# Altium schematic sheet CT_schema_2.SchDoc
size 362 x 192 mm
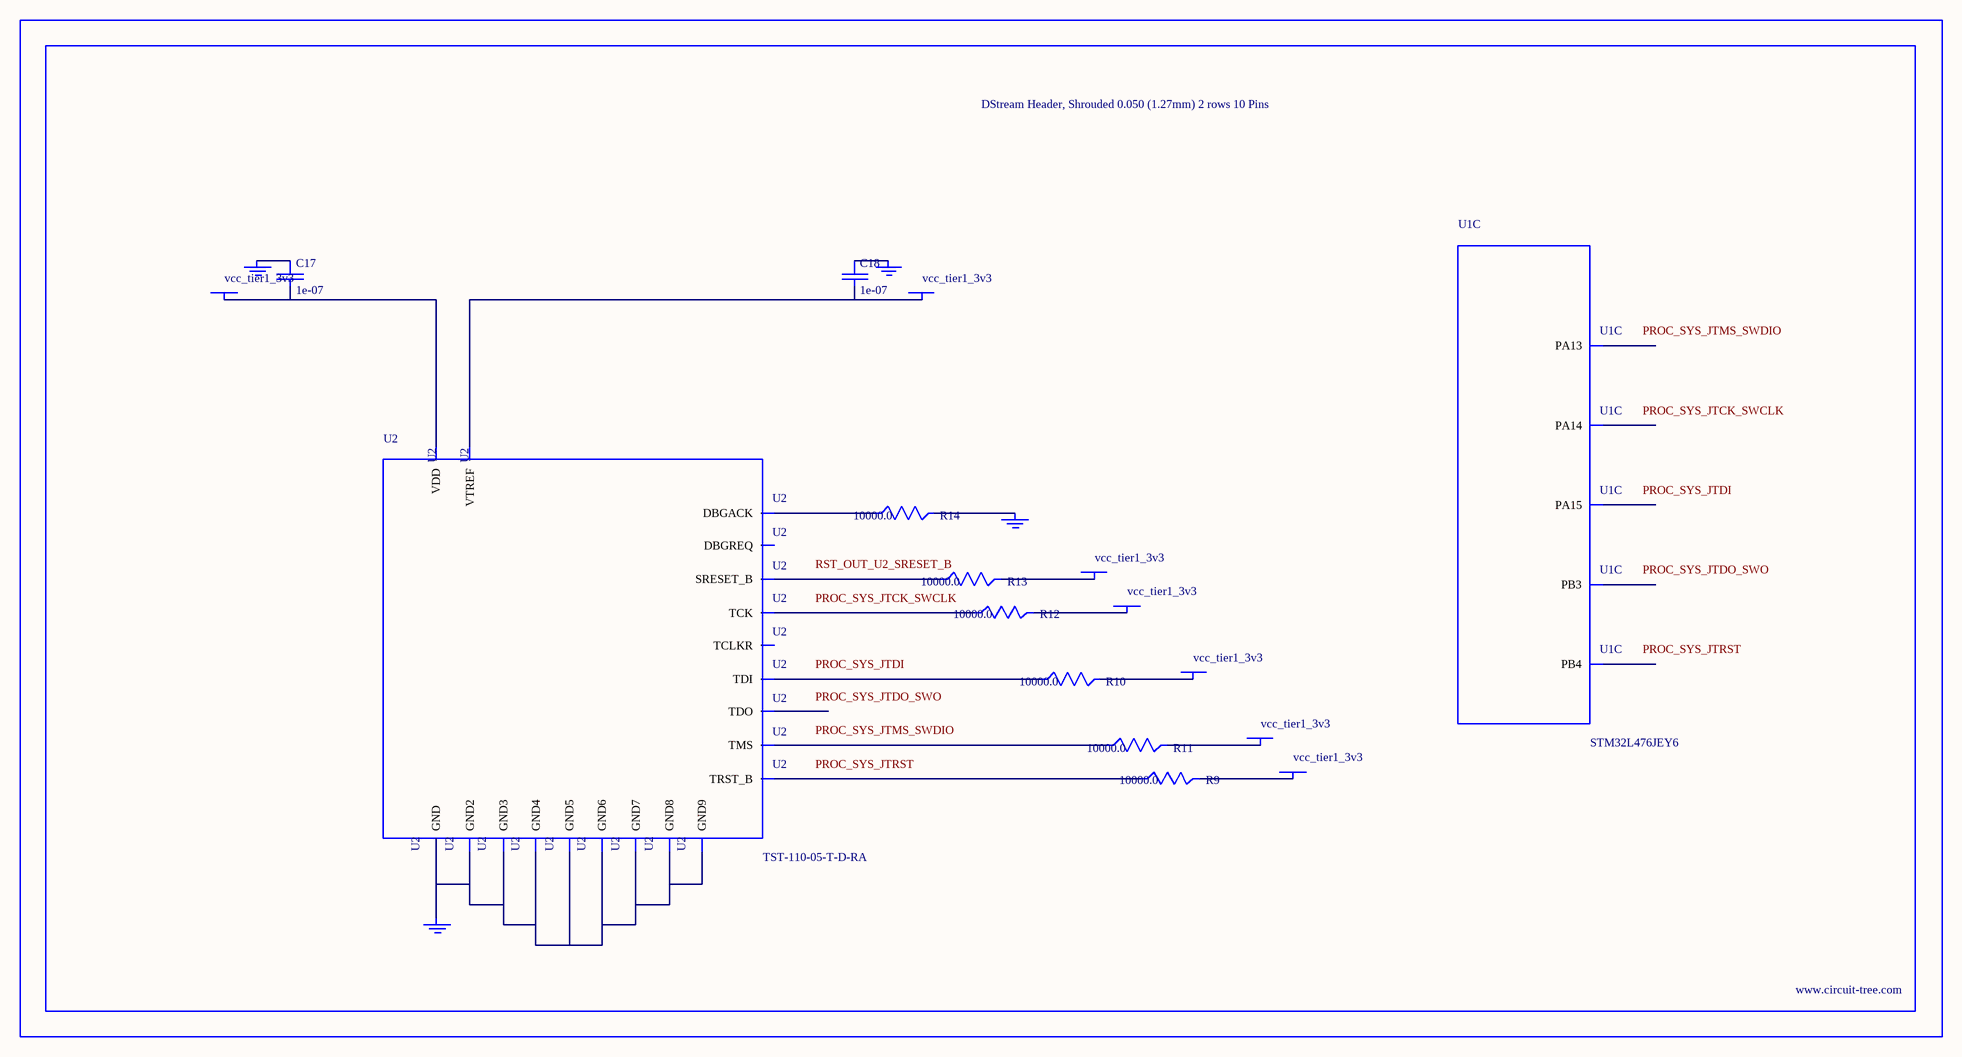
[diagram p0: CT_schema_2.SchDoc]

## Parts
BORDER1  (no value)
C17  1e-07  [C0402]
C18  1e-07  [C0402]
GND_INSTANCE_1_0  (no value)
GND_INSTANCE_1_1  (no value)
GND_INSTANCE_1_2  (no value)
GND_INSTANCE_1_3  (no value)
POWER_INSTANCE_1_0  vcc_tier1_3v3
POWER_INSTANCE_1_1  vcc_tier1_3v3
POWER_INSTANCE_1_2  vcc_tier1_3v3
POWER_INSTANCE_1_3  vcc_tier1_3v3
POWER_INSTANCE_1_4  vcc_tier1_3v3
POWER_INSTANCE_1_5  vcc_tier1_3v3
POWER_INSTANCE_1_6  vcc_tier1_3v3
R9  10000.0  [R0603]
R10  10000.0  [R0603]
R11  10000.0  [R0603]
R12  10000.0  [R0603]
R13  10000.0  [R0603]
R14  10000.0  [R0603]
U1  STM32L476JEY6  [WLCSP72]  (part C of 6)
U2  TST-110-05-T-D-RA  [TST-110-05-T-D-RA]

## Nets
NetC17_1: C17.1 GND_INSTANCE_1_1.0(GND)
NetC17_2: C17.2 POWER_INSTANCE_1_1.0(PWR) U2.2(VDD)
NetC18_1: C18.1 GND_INSTANCE_1_0.0(GND)
NetC18_2: C18.2 POWER_INSTANCE_1_0.0(PWR) U2.1(VTREF)
NetGND_INSTANCE_1_2_0: GND_INSTANCE_1_2.0(GND) R14.2
NetGND_INSTANCE_1_3_0: GND_INSTANCE_1_3.0(GND) U2.4(GND) U2.6(GND2) U2.8(GND3) U2.10(GND4) U2.12(GND5) U2.14(GND6) U2.16(GND7) U2.18(GND8) U2.20(GND9)
NetPOWER_INSTANCE_1_2_0: POWER_INSTANCE_1_2.0(PWR) R9.2
NetPOWER_INSTANCE_1_3_0: POWER_INSTANCE_1_3.0(PWR) R10.2
NetPOWER_INSTANCE_1_4_0: POWER_INSTANCE_1_4.0(PWR) R11.2
NetPOWER_INSTANCE_1_5_0: POWER_INSTANCE_1_5.0(PWR) R12.2
NetPOWER_INSTANCE_1_6_0: POWER_INSTANCE_1_6.0(PWR) R13.2
NetR9_1: R9.1 U2.3(TRST_B)
NetR10_1: R10.1 U2.5(TDI)
NetR11_1: R11.1 U2.7(TMS)
NetR12_1: R12.1 U2.9(TCK)
NetR13_1: R13.1 U2.15(SRESET_B)
NetR14_1: R14.1 U2.19(DBGACK)

Not connected (* = marked no-connect by the designer): U1 A2(PA15) A6(PB3) B2(PA14) C2(PA13) C6(PB4); U2 11(TCLKR) 13(TDO) 17(DBGREQ)

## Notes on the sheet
- Labels drawn without touching a wire or pin: PROC_SYS_JTCK_SWCLK, PROC_SYS_JTDI, PROC_SYS_JTDO_SWO, PROC_SYS_JTMS_SWDIO, PROC_SYS_JTRST, RST_OUT_U2_SRESET_B

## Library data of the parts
BORDER1 = BORDER_PAGE1
C17 C18 = C0402C104K3RACTU
GND_INSTANCE_1_0-GND_INSTANCE_1_3 = GND
POWER_INSTANCE_1_0-POWER_INSTANCE_1_6 = PWR
R9-R14 = RC0603JR-0710KL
